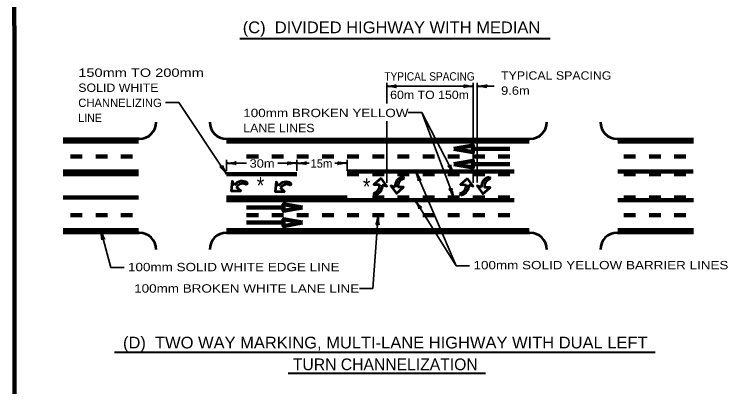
# Model space of a CAD drawing. Extents: x -90 to 765, y -1136 to -592.
# Drawn here: x -32.9 to 218.6, y -990.6 to -857.1 of the extents above; entities that cross this region are included whole.
import ezdxf
from ezdxf.enums import TextEntityAlignment as Align

# ---------------------------------------------------------------- set-up
doc = ezdxf.new("R2010")
doc.units = 0
doc.header["$LTSCALE"] = 1.2
doc.layers.add('1', color=7, linetype='Continuous', lineweight=90)

msp = doc.modelspace()

# ---------------------------------------------------------------- linework, layer by layer
at = {"layer": '1', "lineweight": 40}
for p, q in [((47.874, -865.805), (158.919, -865.805)), ((3.062, -978.196), (196.483, -978.196)), ((65.136, -985.626), (135.772, -985.626))]:
    msp.add_line(p, q, dxfattribs=at)
at = {"layer": '1', "lineweight": 35}
for p, q in [((100.443, -889.079), (100.443, -881.705)), ((100.443, -882.905), (131.419, -882.905)), ((131.419, -917.534), (131.419, -881.705)), ((132.845, -917.407), (132.845, -881.705)), ((132.845, -882.905), (138.845, -882.905)), ((21.236, -888.726), (26.036, -888.726)), ((26.036, -888.726), (43.111, -914.373)), ((108.179, -892.341), (112.979, -892.341)), ((100.443, -917.463), (100.443, -895.457)), ((43.111, -913.173), (43.111, -909.273)), ((43.111, -910.473), (50.263, -910.473)), ((68.311, -913.173), (68.311, -909.273)), ((81.868, -910.473), (86.311, -910.473)), ((86.311, -913.173), (86.311, -909.273)), ((97.411, -929.073), (95.453, -955.405)), ((-1.889, -934.473), (1.674, -947.794)), ((1.674, -947.794), (6.474, -947.794)), ((125.327, -947.201), (130.127, -947.201)), ((90.653, -955.405), (95.453, -955.405))]:
    msp.add_line(p, q, dxfattribs=at)
at = {"layer": '1', "lineweight": 53}
for p, q in [((11.911, -901.773), (-15.389, -901.773)), ((43.111, -901.773), (151.711, -901.773)), ((182.911, -901.773), (210.211, -901.773)), ((95.673, -921.171), (96.014, -921.825)), ((126.649, -921.242), (126.99, -921.895)), ((11.911, -935.373), (-15.389, -935.373)), ((-15.389, -935.373), (11.911, -935.373)), ((43.111, -935.373), (151.711, -935.373)), ((182.911, -935.373), (210.211, -935.373))]:
    msp.add_line(p, q, dxfattribs=at)
at = {"layer": '1'}
for p, q in [((11.611, -902.673), (-15.389, -902.673)), ((43.111, -902.673), (151.411, -902.673)), ((183.211, -902.673), (210.211, -902.673)), ((131.311, -905.373), (144.511, -905.373)), ((-12.689, -908.073), (-8.489, -908.073)), ((-3.689, -908.073), (0.511, -908.073)), ((5.311, -908.073), (9.511, -908.073)), ((50.311, -908.073), (54.511, -908.073)), ((59.311, -908.073), (63.511, -908.073)), ((68.311, -908.073), (72.511, -908.073)), ((77.311, -908.073), (81.511, -908.073)), ((86.311, -908.073), (90.511, -908.073)), ((95.311, -908.073), (99.511, -908.073)), ((104.311, -908.073), (108.511, -908.073)), ((113.311, -908.073), (117.511, -908.073)), ((122.311, -908.073), (126.511, -908.073)), ((131.311, -908.073), (135.511, -908.073)), ((140.311, -908.073), (144.511, -908.073)), ((185.311, -908.073), (189.511, -908.073)), ((194.311, -908.073), (198.511, -908.073)), ((203.311, -908.073), (207.511, -908.073)), ((131.311, -910.773), (144.511, -910.773)), ((-15.389, -913.473), (11.611, -913.473)), ((-15.389, -914.373), (11.611, -914.373)), ((43.111, -914.373), (68.311, -914.373)), ((86.311, -913.473), (146.032, -913.473)), ((86.311, -914.373), (90.511, -914.373)), ((95.311, -914.373), (99.511, -914.373)), ((104.311, -914.373), (108.511, -914.373)), ((113.311, -914.373), (117.511, -914.373)), ((122.311, -914.373), (126.511, -914.373)), ((131.311, -914.373), (135.511, -914.373)), ((140.311, -914.373), (144.511, -914.373)), ((183.211, -913.473), (210.099, -913.473)), ((185.311, -914.373), (189.511, -914.373)), ((194.311, -914.373), (198.511, -914.373)), ((203.311, -914.373), (207.511, -914.373)), ((-15.389, -922.773), (11.611, -922.773)), ((43.111, -922.773), (86.311, -922.773)), ((95.311, -922.773), (99.511, -922.773)), ((104.311, -922.773), (108.511, -922.773)), ((113.311, -922.773), (117.511, -922.773)), ((122.311, -922.773), (126.511, -922.773)), ((131.311, -922.773), (135.511, -922.773)), ((140.311, -922.773), (144.511, -922.773)), ((185.311, -922.773), (189.511, -922.773)), ((194.311, -922.773), (198.511, -922.773)), ((203.311, -922.773), (207.511, -922.773)), ((43.111, -923.673), (146.032, -923.673)), ((183.211, -923.673), (210.211, -923.673)), ((63.511, -926.373), (50.311, -926.373)), ((-12.689, -929.073), (-8.489, -929.073)), ((-3.689, -929.073), (0.511, -929.073)), ((5.311, -929.073), (9.511, -929.073)), ((50.311, -929.073), (54.511, -929.073)), ((59.311, -929.073), (63.511, -929.073)), ((68.311, -929.073), (72.511, -929.073)), ((77.311, -929.073), (81.511, -929.073)), ((86.311, -929.073), (90.511, -929.073)), ((95.311, -929.073), (99.511, -929.073)), ((104.311, -929.073), (108.511, -929.073)), ((113.311, -929.073), (117.511, -929.073)), ((122.311, -929.073), (126.511, -929.073)), ((131.311, -929.073), (135.511, -929.073)), ((140.311, -929.073), (144.511, -929.073)), ((185.311, -929.073), (189.511, -929.073)), ((194.311, -929.073), (198.511, -929.073)), ((203.311, -929.073), (207.511, -929.073)), ((63.511, -931.773), (50.311, -931.773)), ((11.611, -934.473), (-15.389, -934.473)), ((43.111, -934.473), (151.411, -934.473)), ((183.211, -934.473), (210.211, -934.473))]:
    msp.add_line(p, q, dxfattribs=at)
at = {"layer": '1', "lineweight": 158}
msp.add_lwpolyline([(758.78, -598.088), (-32.92, -598.188), (-32.82, -1124.188)], dxfattribs=at)
at = {"layer": '1', "lineweight": 35}
for points in [[(124.411, -914.373), (112.979, -892.341), (124.411, -922.773)], [(61.449, -910.473), (68.311, -910.473), (72.635, -910.473)], [(110.892, -913.473), (125.327, -947.201), (110.64, -923.673)]]:
    msp.add_lwpolyline(points, dxfattribs=at)
at = {"layer": '1'}
for points in [[(124.505, -905.373), (131.311, -906.573), (131.311, -904.173)], [(124.505, -910.773), (131.311, -911.973), (131.311, -909.573)], [(70.316, -926.373), (63.511, -927.573), (63.511, -925.173)], [(70.316, -931.773), (63.511, -932.973), (63.511, -930.573)]]:
    msp.add_lwpolyline(points, close=True, dxfattribs=at)
at = {"layer": '1', "lineweight": 53}
for points in [[(106.639, -916.028), (106.298, -915.374), (106.298, -915.374)], [(137.614, -916.098), (137.274, -915.445), (137.274, -915.445)], [(46.006, -918.318), (45.153, -916.91), (44.808, -920.372), (48.203, -920.38), (46.725, -919.055)], [(50.387, -918.193), (50.565, -917.478), (50.565, -917.477)], [(61.703, -918.572), (60.85, -917.164), (60.506, -920.626), (63.901, -920.634), (62.422, -919.309)], [(66.085, -918.447), (66.263, -917.731), (66.263, -917.731)], [(98.407, -915.842), (95.859, -918.085), (97.845, -918.098)], [(98.871, -918.174), (100.443, -918.663), (98.407, -915.842)], [(129.383, -915.913), (126.835, -918.156), (128.82, -918.169)], [(129.847, -918.244), (131.419, -918.734), (129.383, -915.913)], [(103.441, -919.025), (101.869, -918.536), (103.905, -921.357), (106.453, -919.113), (104.467, -919.1)], [(134.417, -919.096), (132.845, -918.607), (134.881, -921.428), (137.429, -919.184), (135.443, -919.171)]]:
    msp.add_lwpolyline(points, dxfattribs=at)
for centre, radius, start, end in [((11.911, -895.773), 6, 270, 0), ((43.111, -895.773), 6, 180, 270), ((151.711, -895.773), 6, 270, 0), ((182.911, -895.773), 6, 180, 270), ((106.73, -918.656), 3.31, 97.50474, 186.40595), ((137.706, -918.727), 3.31, 97.50474, 186.40595), ((48.714, -920.222), 3.31, 55.99914, 144.90034), ((48.984, -920.441), 2.651, 58.03029, 148.46133), ((64.411, -920.476), 3.31, 55.99914, 144.90034), ((64.681, -920.695), 2.651, 58.03029, 148.46133), ((95.234, -918.557), 2.651, 279.53589, 9.96693), ((107.078, -918.642), 2.651, 99.53589, 189.96693), ((138.054, -918.712), 2.651, 99.53589, 189.96693), ((95.582, -918.543), 3.31, 277.50474, 6.40595), ((126.21, -918.628), 2.651, 279.53589, 9.96693), ((126.557, -918.613), 3.31, 277.50474, 6.40595), ((11.911, -941.373), 6, 0, 90), ((43.111, -941.373), 6, 90, 180), ((151.711, -941.373), 6, 0, 90), ((182.911, -941.373), 6, 90, 180)]:
    msp.add_arc(centre, radius, start, end, dxfattribs=at)
at = {"layer": '1', "lineweight": 40}
for centre, major_axis, ratio, start_param, end_param in [((101.788, -883.159), (-2.108, 0.211), 0.07063, 3.1407148, 5.41811), ((101.753, -882.574), (-2.143, -0.187), 0.122415, 0.8963533, 3.1415927), ((130.109, -883.237), (2.143, 0.187), 0.122415, 0.8963533, 3.1415927), ((130.074, -882.651), (2.108, -0.211), 0.07063, 3.1407148, 5.41811), ((134.189, -883.159), (-2.108, 0.211), 0.07063, 3.1407148, 5.41811), ((134.154, -882.574), (-2.143, -0.187), 0.122415, 0.8963533, 3.1415927), ((44.455, -910.727), (-2.108, 0.211), 0.07063, 3.1407148, 5.41811), ((44.455, -910.727), (-2.108, 0.211), 0.07063, 3.1407148, 5.41811), ((44.42, -910.141), (-2.143, -0.187), 0.122415, 0.8963533, 3.1415927), ((44.42, -910.141), (-2.143, -0.187), 0.122415, 0.8963533, 3.1415927), ((67.001, -910.804), (2.143, 0.187), 0.122415, 0.8963533, 3.1415927), ((67.001, -910.804), (2.143, 0.187), 0.122415, 0.8963533, 3.1415927), ((66.966, -910.219), (2.108, -0.211), 0.07063, 3.1407148, 5.41811), ((66.966, -910.219), (2.108, -0.211), 0.07063, 3.1407148, 5.41811), ((69.655, -910.727), (-2.108, 0.211), 0.07063, 3.1407148, 5.41811), ((69.655, -910.727), (-2.108, 0.211), 0.07063, 3.1407148, 5.41811), ((69.62, -910.141), (-2.143, -0.187), 0.122415, 0.8963533, 3.1415927), ((69.62, -910.141), (-2.143, -0.187), 0.122415, 0.8963533, 3.1415927), ((85.001, -910.804), (2.143, 0.187), 0.122415, 0.8963533, 3.1415927), ((84.966, -910.219), (2.108, -0.211), 0.07063, 3.1407148, 5.41811), ((42.109, -913.467), (1.343, -1.68), 0.122415, 0.8963533, 3.1415927), ((42.577, -913.113), (0.993, -1.871), 0.07063, 3.1407148, 5.41811), ((123.513, -913.363), (1.153, -1.816), 0.122415, 0.8963533, 3.1415927), ((123.513, -913.363), (1.153, -1.816), 0.122415, 0.8963533, 3.1415927), ((124.017, -913.062), (0.784, -1.968), 0.07063, 3.1407148, 5.41811), ((124.017, -913.062), (0.784, -1.968), 0.07063, 3.1407148, 5.41811), ((111.188, -914.809), (-0.636, 2.021), 0.07063, 3.1407148, 5.41811), ((111.188, -914.809), (-0.636, 2.021), 0.07063, 3.1407148, 5.41811), ((111.712, -914.546), (-1.015, 1.896), 0.122415, 0.8963533, 3.1415927), ((111.712, -914.546), (-1.015, 1.896), 0.122415, 0.8963533, 3.1415927), ((123.64, -921.664), (0.929, -1.94), 0.122415, 0.8963533, 3.1415927), ((124.176, -921.425), (0.544, -2.047), 0.07063, 3.1407148, 5.41811), ((111.136, -924.948), (-0.937, 1.9), 0.07063, 3.1407148, 5.41811), ((111.614, -924.608), (-1.294, 1.719), 0.122415, 0.8963533, 3.1415927), ((97.058, -930.395), (0.366, 2.086), 0.07063, 3.1407148, 5.41811), ((97.644, -930.403), (-0.028, 2.151), 0.122415, 0.8963533, 3.1415927), ((-1.787, -935.837), (-0.341, 2.091), 0.07063, 3.1407148, 5.41811), ((-1.787, -935.837), (-0.341, 2.091), 0.07063, 3.1407148, 5.41811), ((-1.231, -935.652), (-0.735, 2.022), 0.122415, 0.8963533, 3.1415927), ((-1.231, -935.652), (-0.735, 2.022), 0.122415, 0.8963533, 3.1415927)]:
    msp.add_ellipse(centre, major_axis=major_axis, ratio=ratio, start_param=start_param, end_param=end_param, dxfattribs=at)

# ---------------------------------------------------------------- texts
at = {"layer": '1'}
for s, height, width, p in [('(C)  DIVIDED HIGHWAY WITH MEDIAN', 4.2, 1.05, (48.925, -863.915)), ('150mm TO 200mm', 3, 1.3, (-9.937, -879.547)), ('TYPICAL SPACING', 3, 1.1, (141.373, -880.571)), ('SOLID WHITE', 3, 1.1, (-9.937, -884.947)), ('9.6m', 3, 1.15, (141.373, -885.971)), ('LINE', 3, 0.95, (-9.937, -895.747)), ('100mm BROKEN YELLOW', 3, 1.2, (49.105, -893.975)), ('LANE LINES', 3, 1.1, (49.105, -899.375)), ('100mm SOLID YELLOW BARRIER LINES', 3, 1.2, (131.502, -948.481)), ('100mm SOLID WHITE EDGE LINE', 3, 1.2, (7.858, -949.179)), ('100mm BROKEN WHITE LANE LINE', 3, 1.2, (10.061, -956.831))]:
    msp.add_text(s, height=height, dxfattribs=dict(at, width=width)).set_placement(p)
for s, height, width, p in [('TYPICAL SPACING', 3, 0.9, (115.773, -880.892)), ('60m TO 150m', 3, 1.1, (115.774, -887.492)), ('30m', 3, 1.15, (55.841, -912.077)), ('*', 6, 0.85, (55.278, -921.458)), ('*', 6, 0.85, (93.246, -921.877)), ('(D)  TWO WAY MARKING, MULTI-LANE HIGHWAY WITH DUAL LEFT', 4.2, 1.05, (99.932, -976.821))]:
    msp.add_text(s, height=height, dxfattribs=dict(at, width=width)).set_placement(p, align=Align.CENTER)
msp.add_text('CHANNELIZING', height=3, dxfattribs=at).set_placement((-9.937, -890.347))
for s, height, p in [('15m', 3, (77.081, -912.077)), ('TURN CHANNELIZATION', 4.2, (99.932, -984.62))]:
    msp.add_text(s, height=height, dxfattribs=at).set_placement(p, align=Align.CENTER)

doc.saveas('drawing.dxf')
